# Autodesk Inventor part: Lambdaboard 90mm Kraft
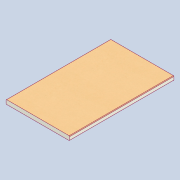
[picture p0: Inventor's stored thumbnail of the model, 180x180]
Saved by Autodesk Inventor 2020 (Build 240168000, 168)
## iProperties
Created: 2020-11
Part Number: Lambdaboard 90mm Kraft
Material: Polyisocyanurate
Document SubType Name: Modeling
Designer: Yolande
Density: 0.032 g/cm^3
Appearance: Pink
Author: Yolande
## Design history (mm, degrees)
sketch "Sketch1"
  geometry: L1 (10, 0)-(1210, 0); L2 (1220, 10)-(1220, 70); L3 (1210, 80)-(10, 80); L4 (0, 70)-(0, 10); A1 r 10 centre (10, 70) between (10, 80) and (0, 70); A2 r 10 centre (10, 10) between (0, 10) and (10, 0); A3 r 10 centre (1210, 70) between (1220, 70) and (1210, 80); A4 r 10 centre (1210, 10) between (1210, 0) and (1220, 10); 3 further points
  constraints: 8 end point, 8 point on circle, 8 tangent, 6 point on line, 4 centre point, 3 equal radius, 3 perpendicular, 1 horizontal
  dimensions: "d0" = 1220 distance of point (0, 0) point (1220, 0); "d1" = 80 distance of point (1220, 0) point (1220, 80); "d2" = 10 radius of A1
extrude "Extrusion1" new body sketch "Sketch1" distance "d3" = 2000; taper "d4" = 0 deg
body "Solid1"
